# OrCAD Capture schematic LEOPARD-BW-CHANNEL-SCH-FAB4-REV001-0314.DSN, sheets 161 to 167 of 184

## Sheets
161 122_SMBUS (2/4): size A3; title: SMBUS (2/4)
162 124_SMBUS (4/4): size A3; title: SMBUS (4/4)
163 047_CPU2 - QPI (1/2): size A3; title: CPU2 - QPI (1/2)
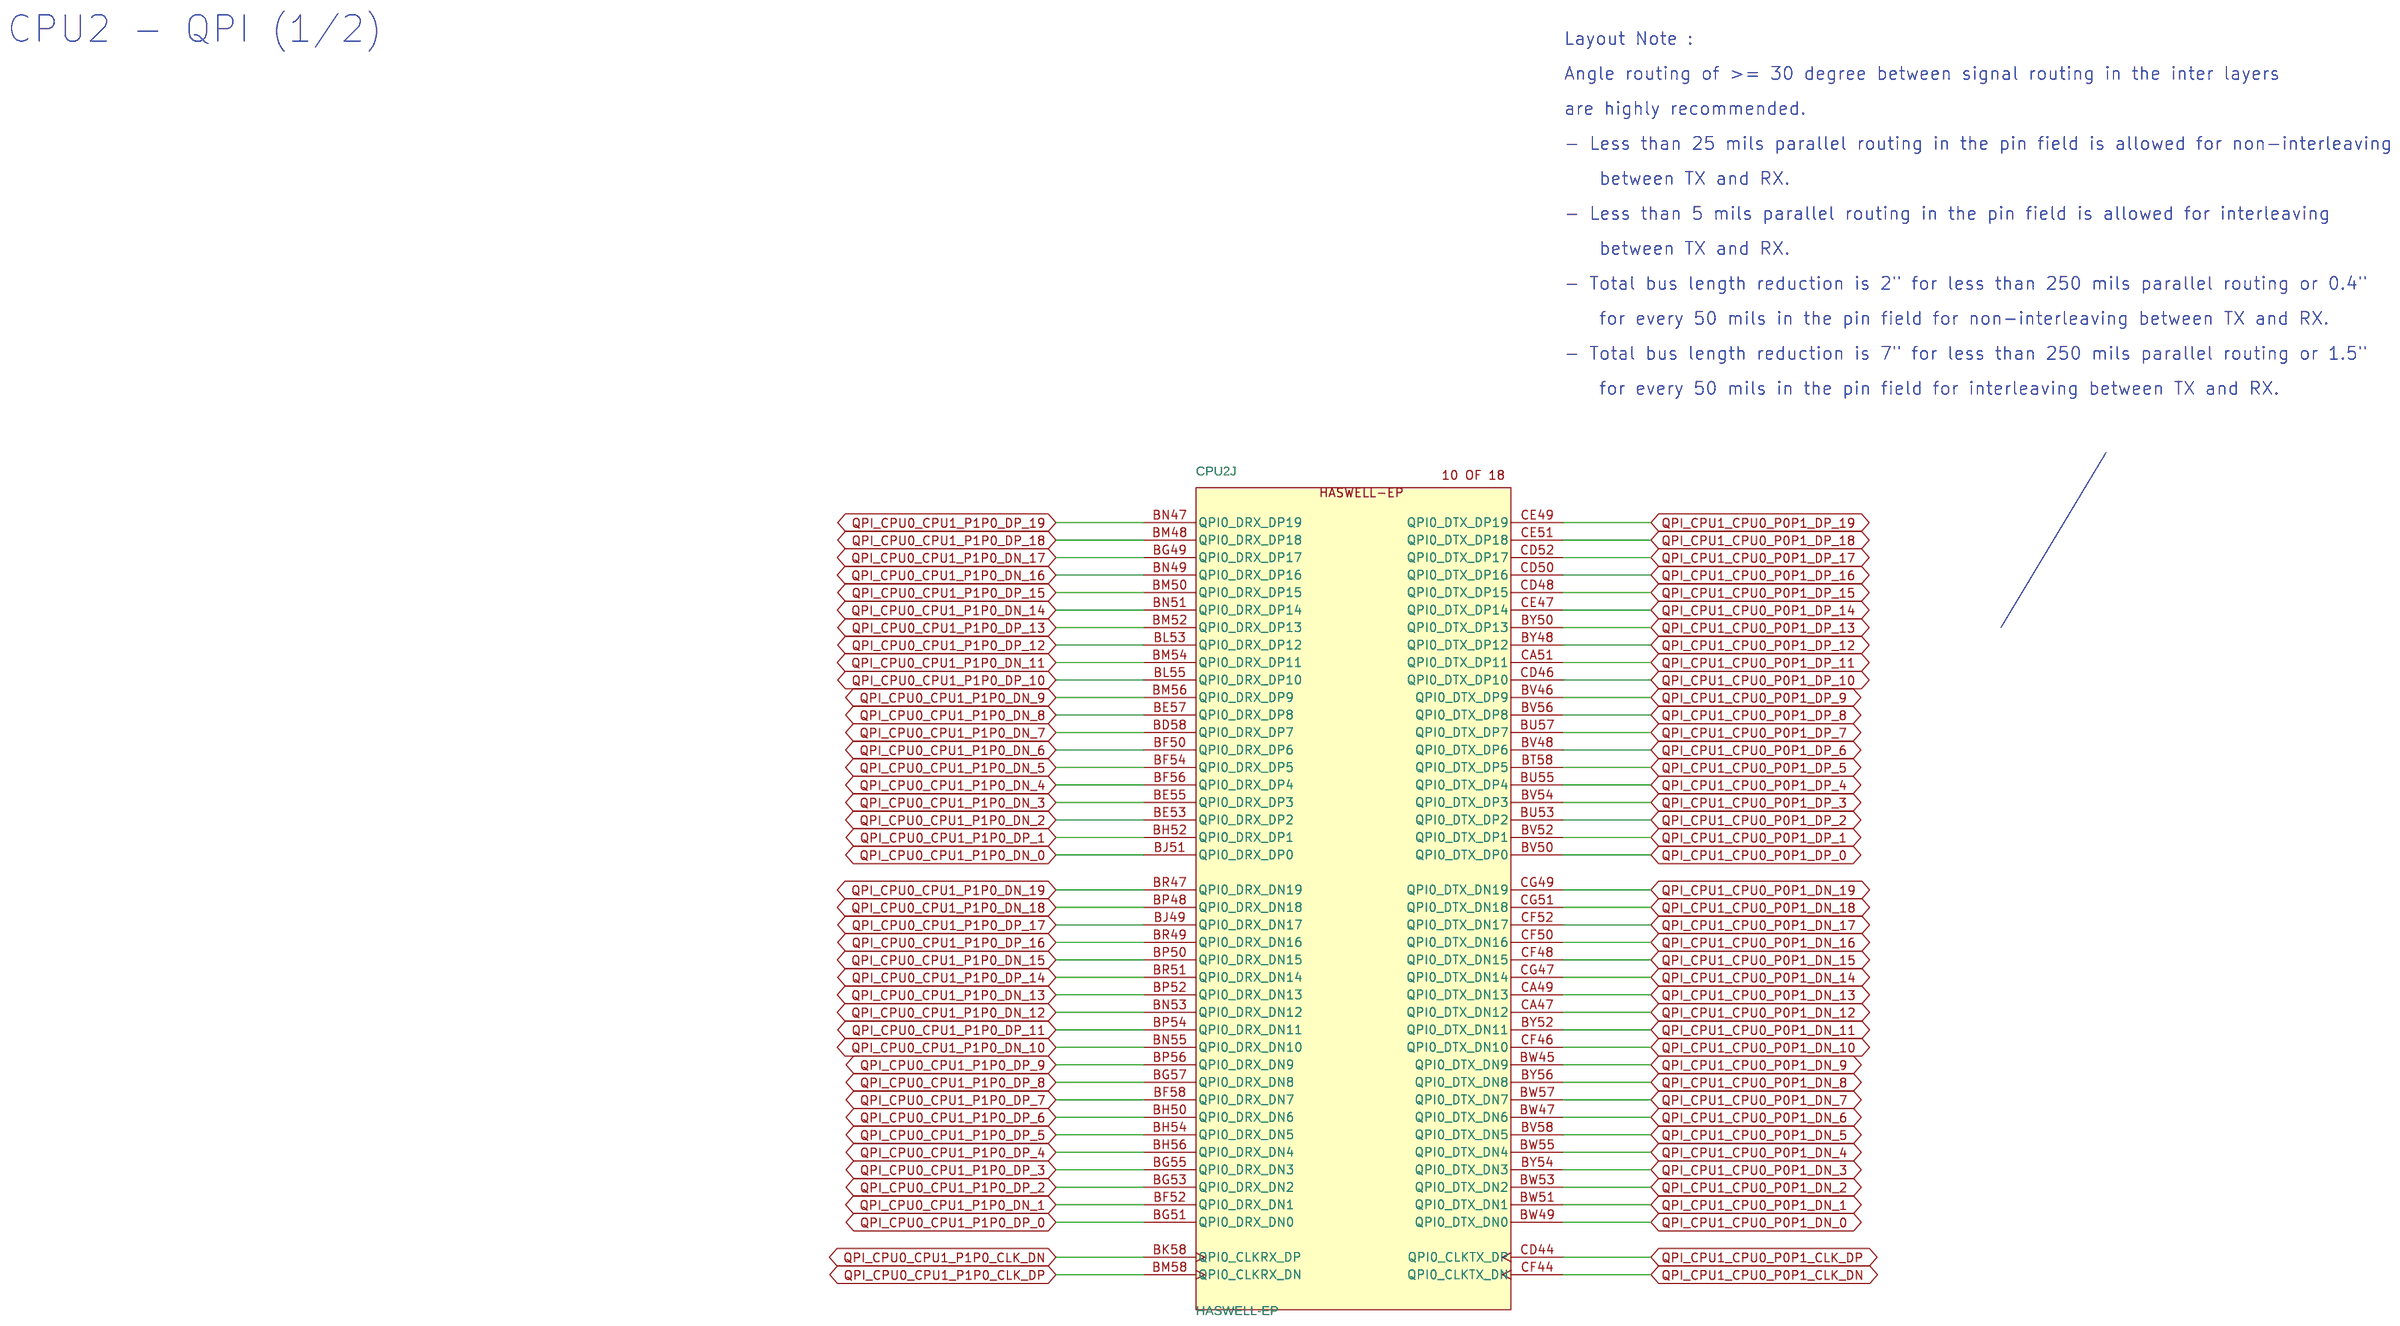
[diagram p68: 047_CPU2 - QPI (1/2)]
164 033_CPU1 - QPI (1/2): size A3; title: CPU1 - QPI (1/2)
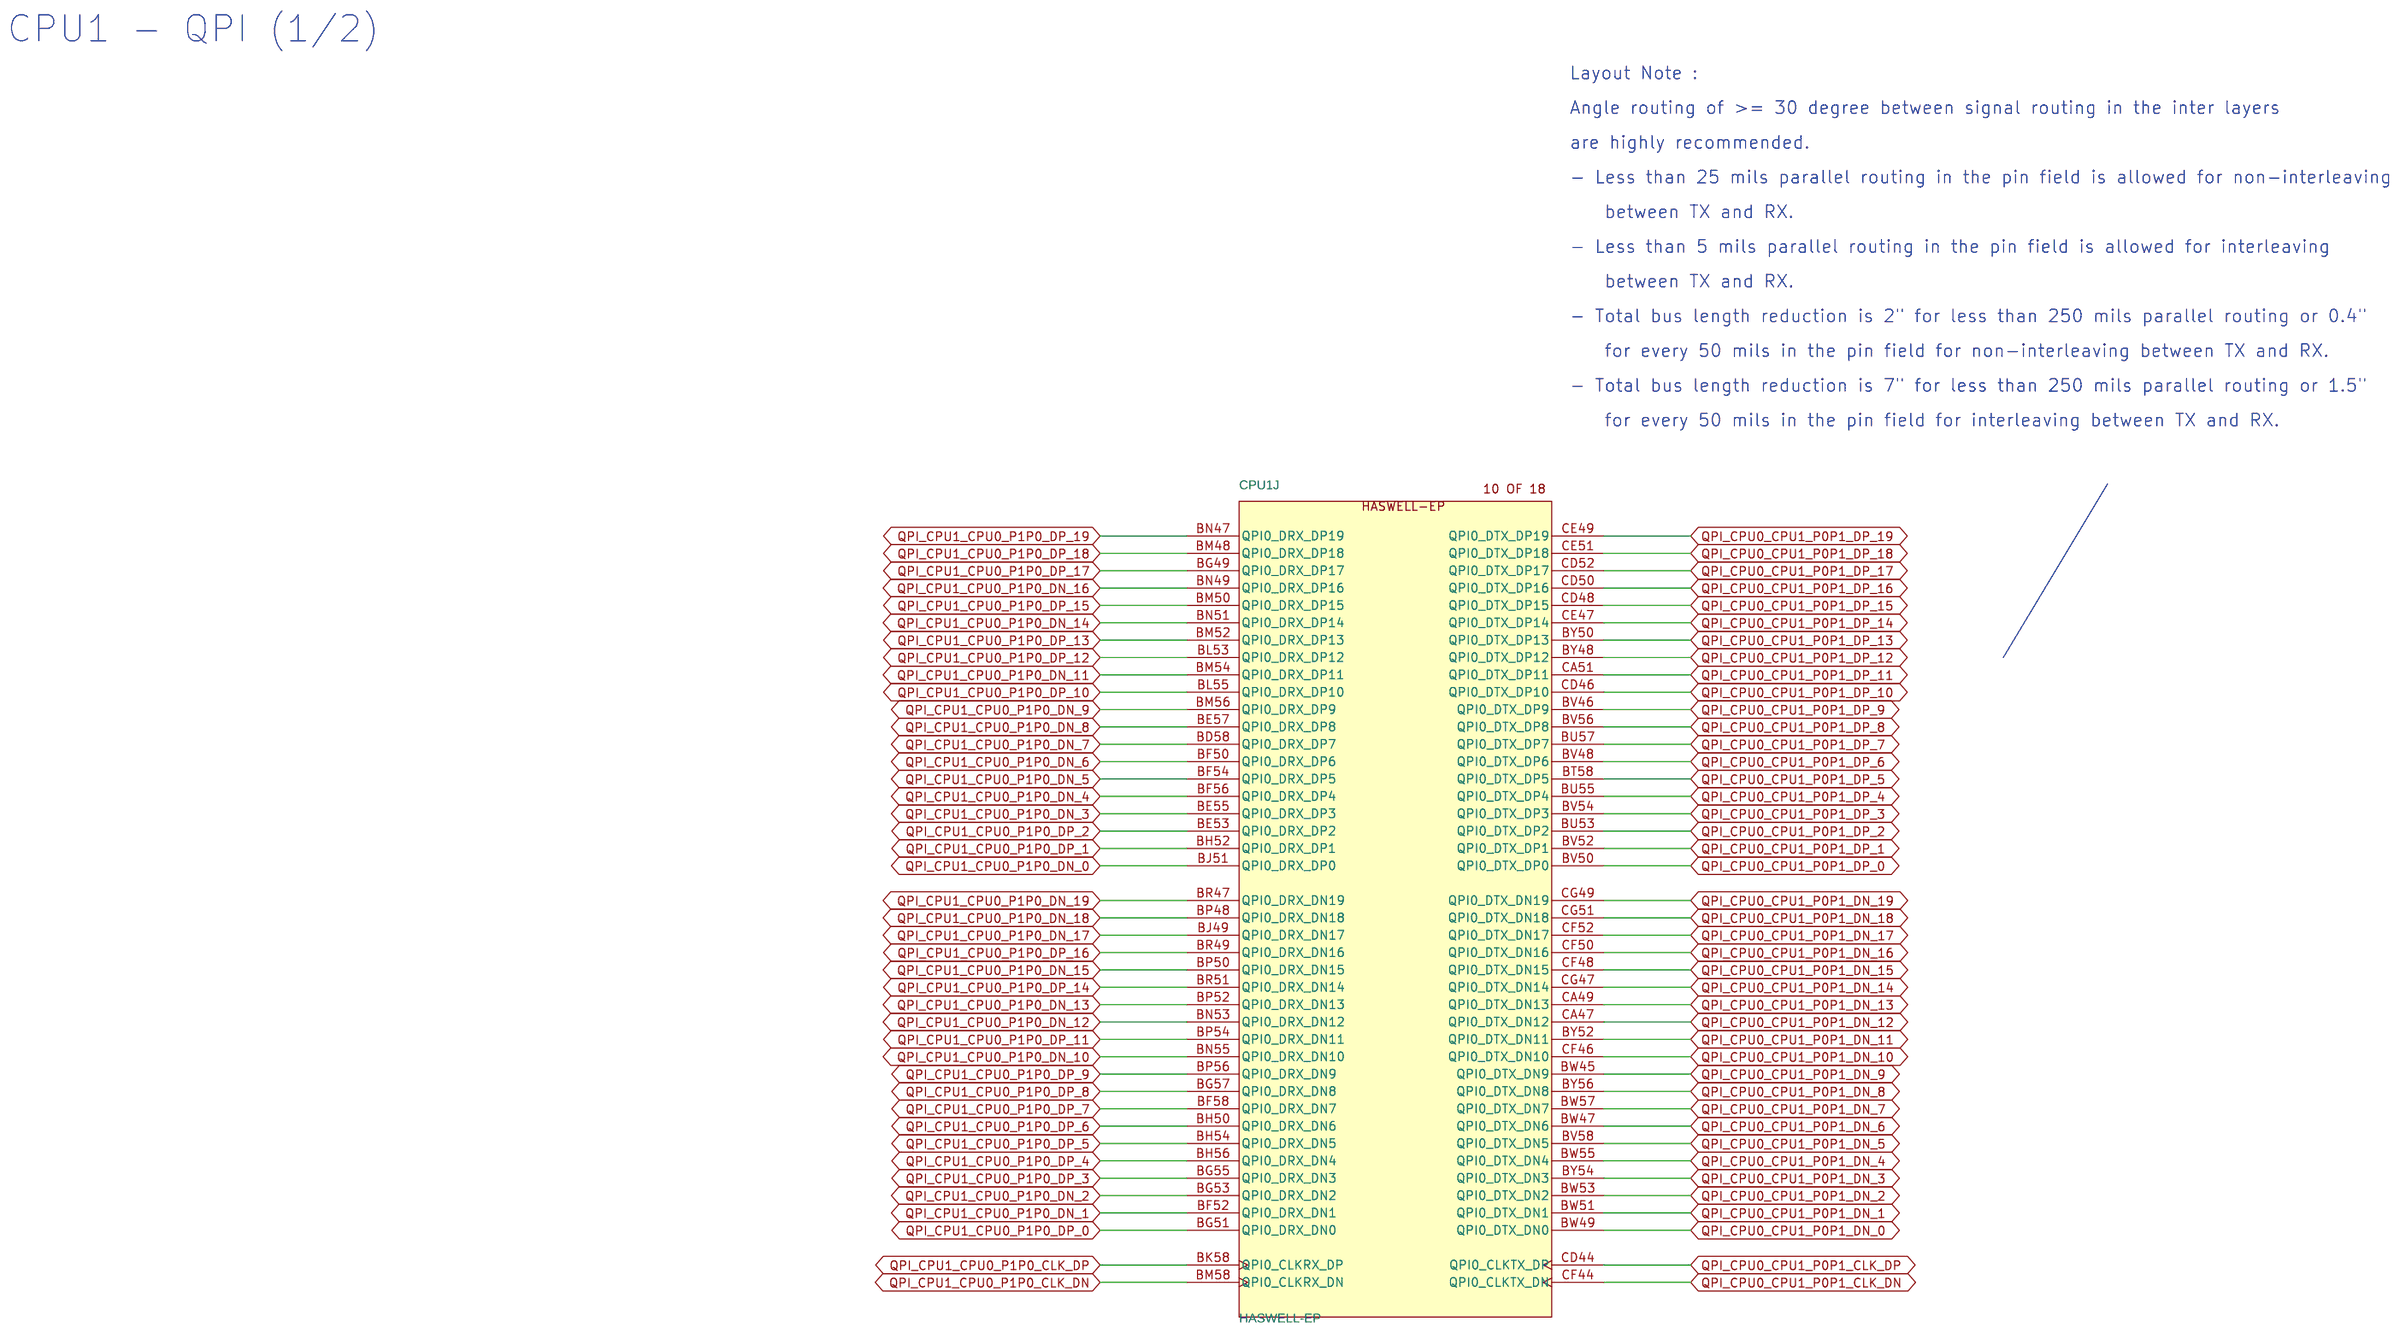
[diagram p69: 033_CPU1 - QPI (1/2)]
165 034_CPU1 - QPI (2/2): size A3; title: CPU1 - QPI (2/2)
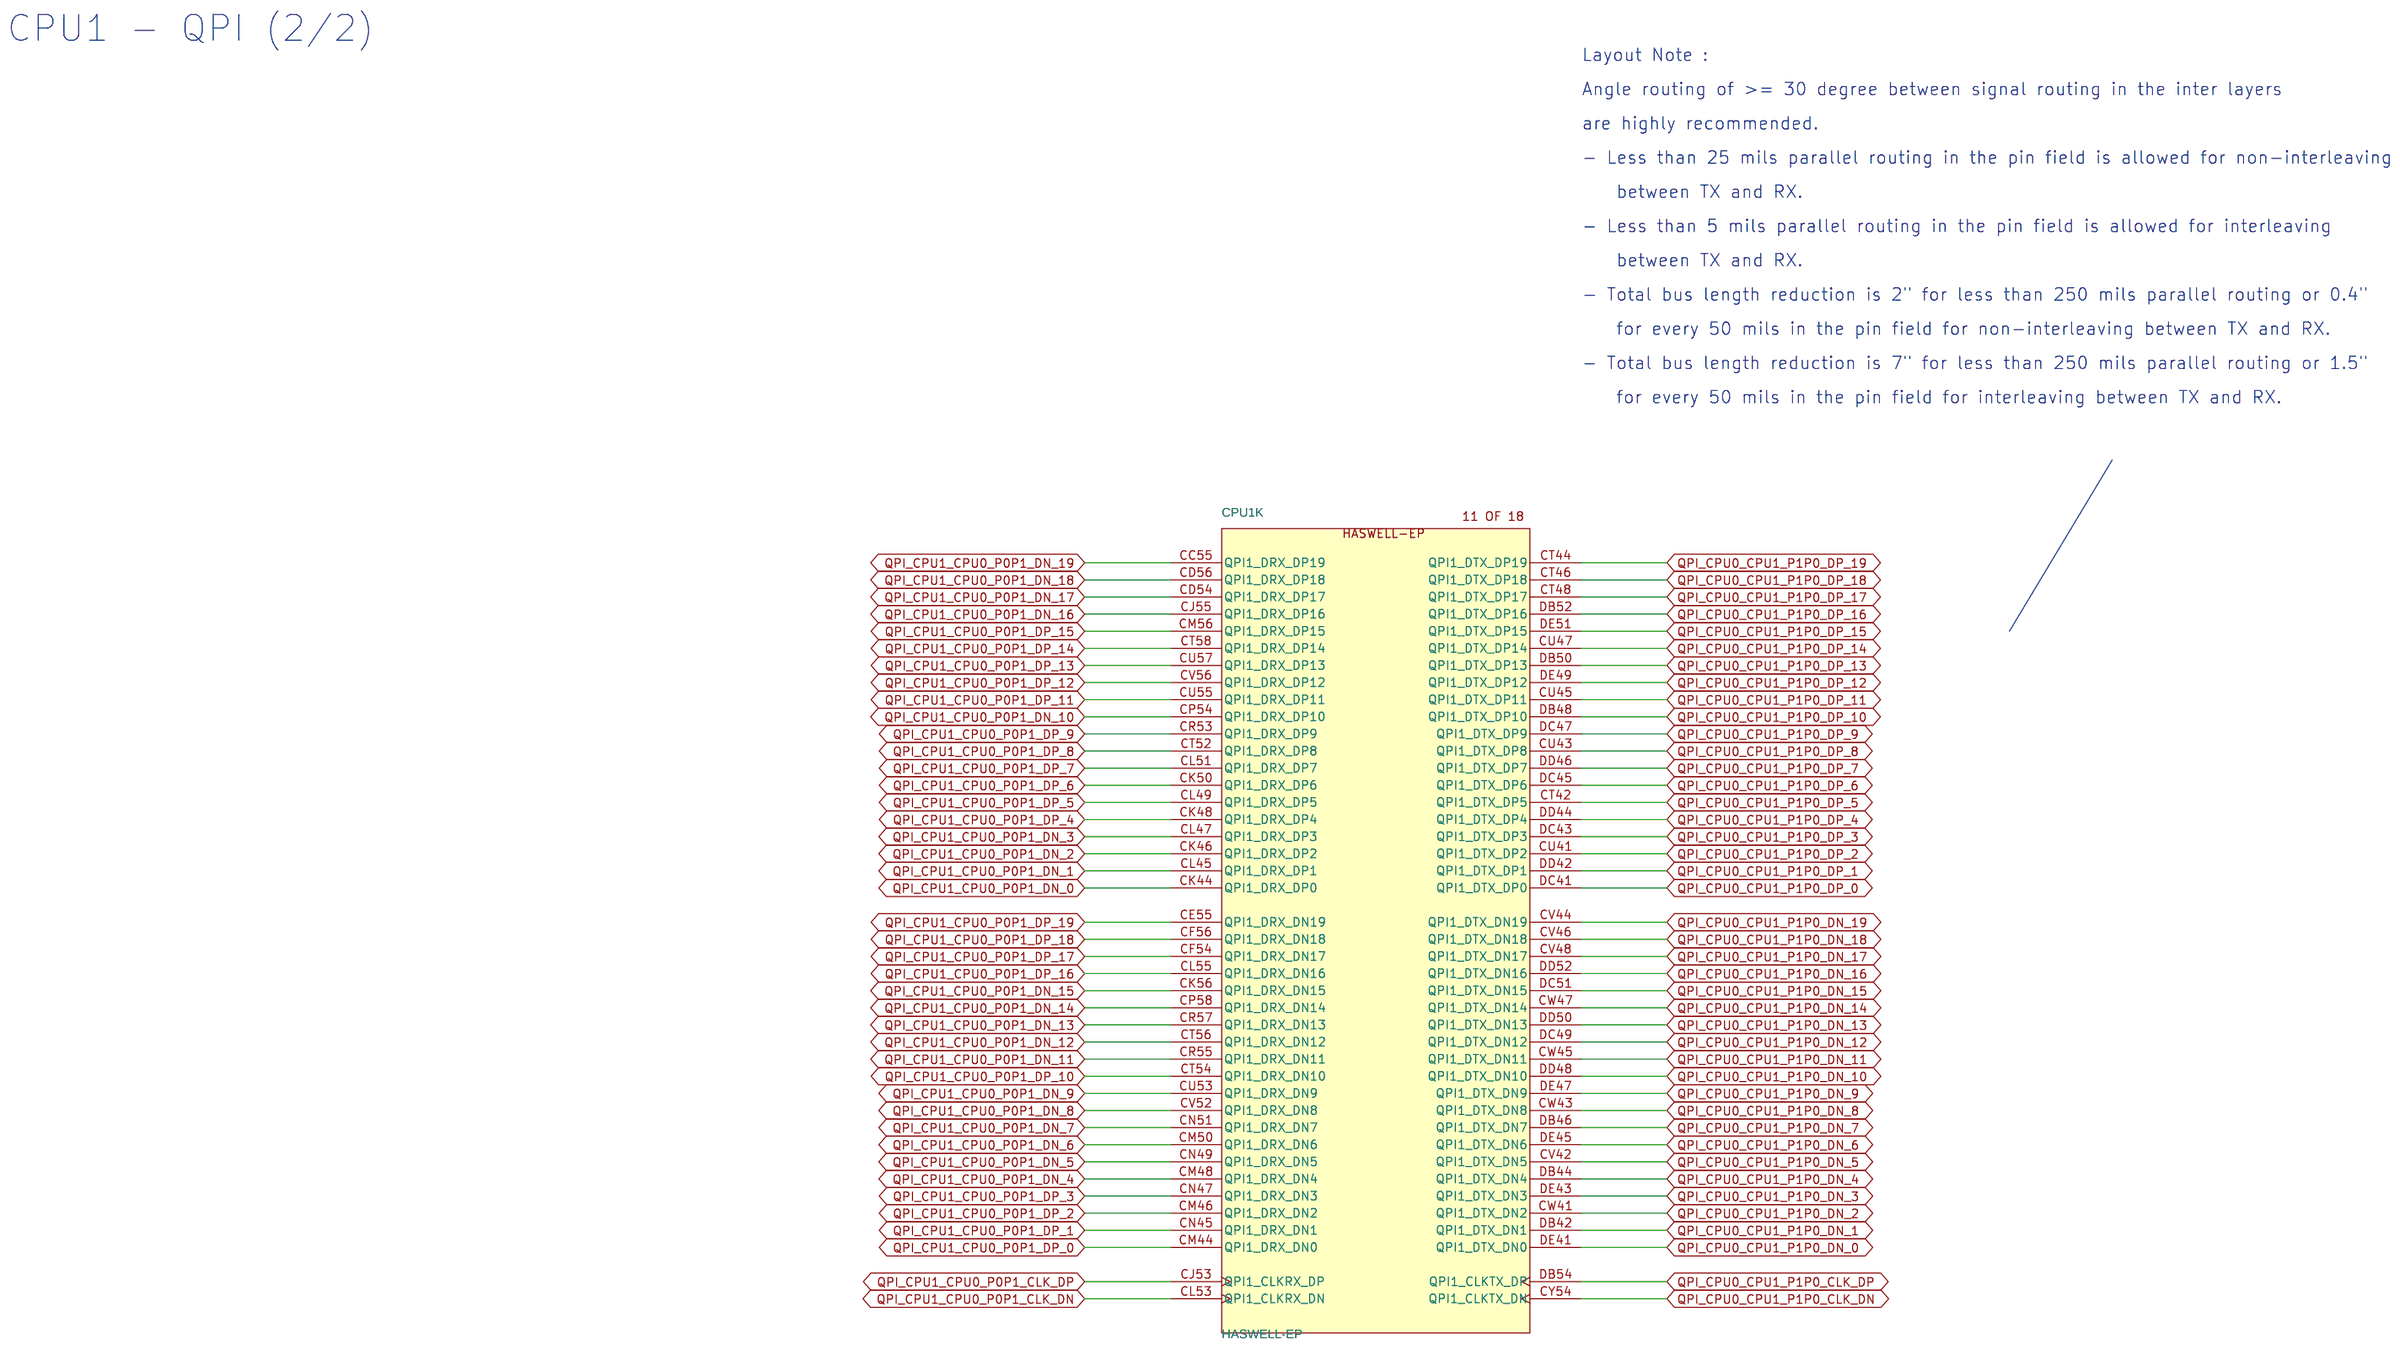
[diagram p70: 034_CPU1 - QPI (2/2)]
166 082_WBG - CLOCK/MICS: size A3; title: WBG - CLOCK/MICS
167 048_CPU2 - QPI (2/2): size A3; title: CPU2 - QPI (2/2)
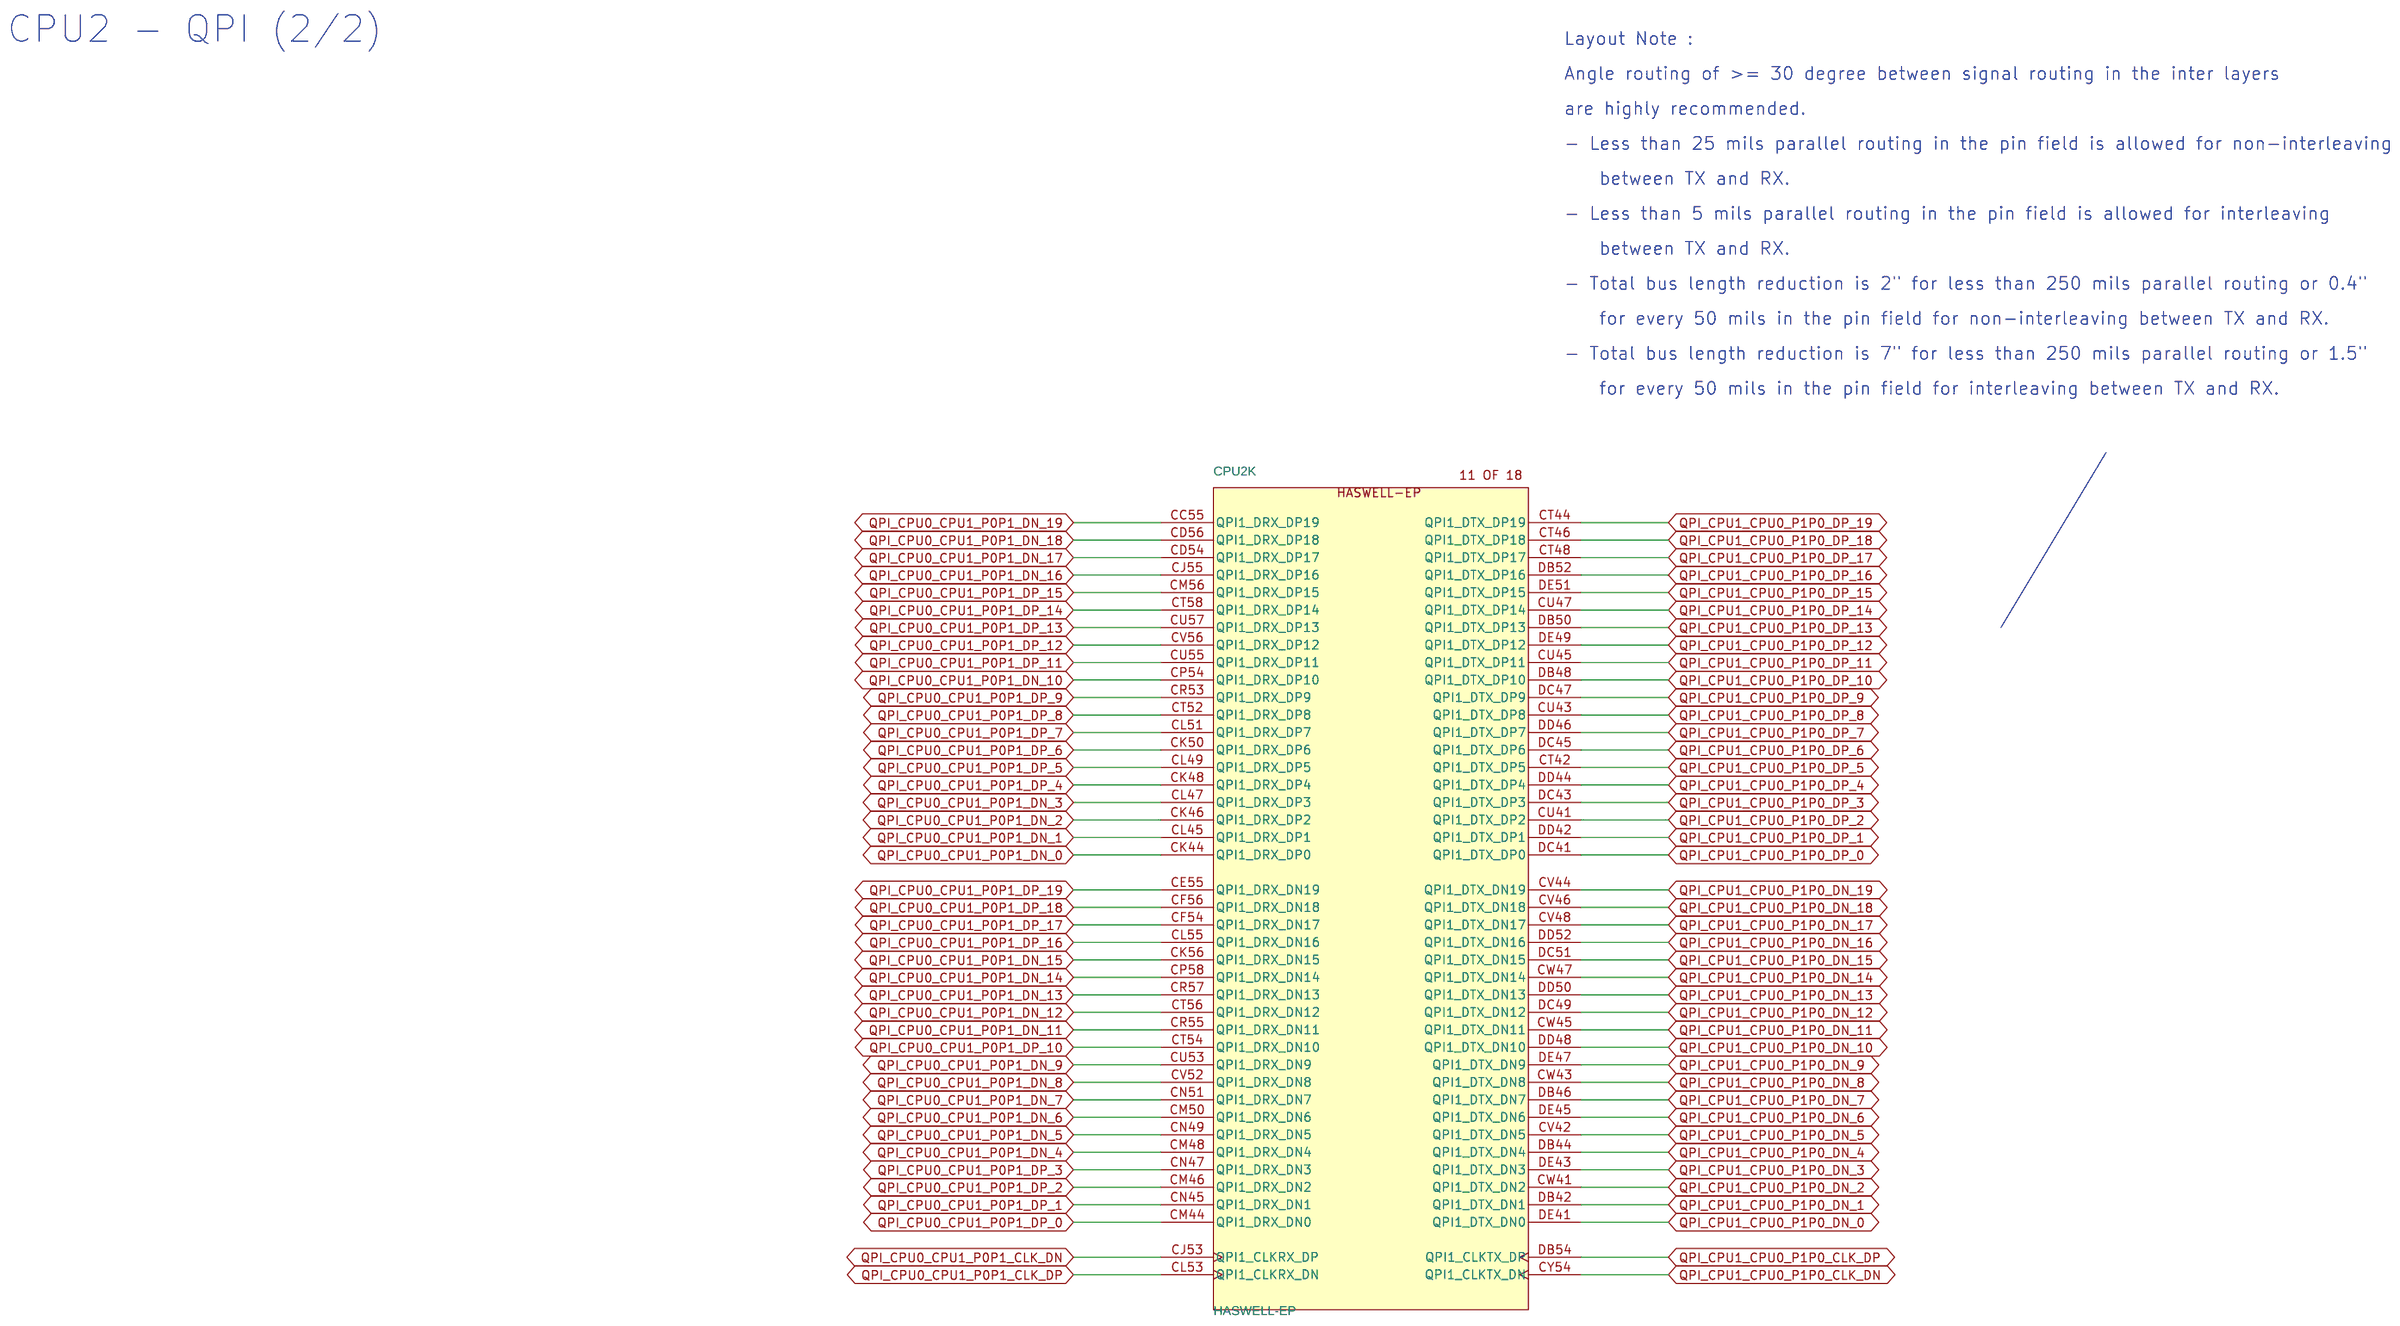
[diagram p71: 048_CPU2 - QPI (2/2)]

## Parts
sheet 035_CPU1 - VCCIN & VDDQ
CPU1  HASWELL-EP  [SKT-LGA2011M6151-1H298]  (sections A,B,C,D,E,F,G,H,I,J,K,L,M,N,O,P,Q,R)
sheet 041_CPU2 - DDR4 (CHANNEL F)
CPU2  HASWELL-EP  [SKT-LGA2011M6151-1H298]  (sections A,B,C,D,E,F,G,H,I,J,K,L,M,N,O,P,Q,R)
sheet 082_WBG - CLOCK/MICS
JP7  FCI-CON2-S-GP  [680001-202HLF]
R130  7K5R2F-1-GP  [R402H16]
R131  7K5R2F-1-GP  [R402H16]
R132  22D6R2F-L1-GP  [R402H16]
R133  7K5R2F-1-GP  [R402H16]
R134  10KR2F-2-GP  [R402H16]
R135  10KR2F-2-GP  [R402H16]
R136  7K5R2F-1-GP  [R402H16]
R137  10KR2F-2-GP  [R402H16]
R188  10KR2F-2-GP  [R402H16]
R193  10KR2F-2-GP  [R402H16]
R197  10KR2F-2-GP  [R402H16]
R251  2K2R2F-GP  [R402H16]
R256  1KR2F-3-GP  [R402H16]
R363  1KR2F-3-GP  [R402H16]
R365  10KR2F-2-GP  [R402H16]
R398  10KR2F-2-GP  [R402H16]
R499  0R2J-2-GP  [R402H16]
R706  10KR2F-2-GP  [R402H16]
R732  10KR2F-2-GP  [R402H16]
R843  10KR2F-2-GP  [R402H16]
R845  10KR2F-2-GP  [R402H16]
R847  10KR2F-2-GP  [R402H16]
R848  0R3J-0-U-GP  [R603H22]
R1206  10KR2F-2-GP  [R402H16]
TP184  TPAD24  [TPAD24]
sheet 083_WBG - DMI & USB
WBG1  WELLSBURG-1-GP-U  [BGA836M25H87]  (sections A,B,C,D,E,F,G,H,I,J,K)
sheet 122_SMBUS (2/4)
C505  SC1KP50V2KX-1GP  [C402H22]
C506  SC1KP50V2KX-1GP  [C402H22]
R616  1KR2F-3-GP  [R402H16]
R617  1KR2F-3-GP  [R402H16]
R618  4K7R2F-GP  [R402H16]
R619  4K7R2F-GP  [R402H16]
R622  4K7R2F-GP  [R402H16]
R623  4K7R2F-GP  [R402H16]
R874  1KR2F-3-GP  [R402H16]
R875  1KR2F-3-GP  [R402H16]
R876  4K7R2F-GP  [R402H16]
R877  4K7R2F-GP  [R402H16]
R878  4K7R2F-GP  [R402H16]
R879  4K7R2F-GP  [R402H16]
U41  NTJD4001NT1G-1-GP  [SOT-363H44]
sheet 124_SMBUS (4/4)
R717  0R2J-2-GP  [R402H16]
R721  0R2J-2-GP  [R402H16]

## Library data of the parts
CPU1 CPU2 = HASWELL-EP: SKT CPU LGA 2011P AZIF0001-P004C SMD; GREENDFACTOR: R2_C;; POP?: 62.10079.311; Package Type: SOCKET-G2; Part Number: 62.10079.261; SPEC: http://wpqssvr.wistron.com.tw:7001/wpqs/servlet/COM.qpart.Attachment?PartNumber=62.10079.261
JP7 = FCI-CON2-S-GP: HEAD ML 1R2P 68001-202HLF; GREENDFACTOR: R2_SA;; Part Number: 21.65007.102; Part Type: CONN-G4; SPEC: http://wpqssvr.wistron.com.tw:7001/wpqs/servlet/COM.qpart.Attachment?PartNumber=21.65007.102
R130 R131 R133 R136 = 7K5R2F-1-GP: CHIP RES 7.5K F 1/16W 0402; Category: PCH; Part Number: 64.75015.6DL; Part Type: SMD-RG
R132 = 22D6R2F-L1-GP: CHIP RES 22.6 F 1/16W 0402; Category: PCH; GREENDFACTOR: R2_SA;HF_SA;G_SA;; Package Type: SMD-RG; Part Number: 64.22R65.6DL; Quotation: 2_3; Type: SMD
R134 R135 R137 R188 R193 R197 R398 R1206 = 10KR2F-2-GP: CHIP RES 10K F 1/16W 0402; Category: PCH; DESCRIPTIO: CHIP RES 10K F 1/16W 0402; GREENDFACTOR: R2_SA;HF_SA;G_SA;; Package Type: SMD-RG; Part Number: 64.10025.6DL; Part Type: SMD-RG; SPEC: http://wpqssvr.wistron.com.tw:7001/wpqs/servlet/COM.qpart.Attachment?PartNumber=64.10025.6DL; VENDORPARTNUMBER: RM04FTN1002 / RTT021002FTH / RR0510S-103-FN / RC0402FR-0710KL/WR04X1002FTL
R251 = 2K2R2J-2-GP: CHIP RES 2.2K F 1/16W 0402; Category: BMC; DESCRIPTIO: CHIP RES 2.2K J 1/16W 0402; GREENDFACTOR: R2_SA;HF_SA;G_SA;; Package Type: RCL_GP; Part Number: 64.22015.6DL; Part Type: RCL_GP; SPEC: http://wpqssvr.wistron.com.tw:7001/wpqs/servlet/COM.qpart.Attachment?PartNumber=64.22015.6DL; VENDORPARTNUMBER: RM04FTN2201/RTT022201FTH/RR0510S-222-FN/RC0402FR-072K2L
R256 = 1KR2F-3-GP: CHIP RES 1K F 1/16W 0402; Category: PCH; GREENDFACTOR: R2_SA;HF_SA;G_SA;; Package Type: SMD-RG; Part Number: 64.10015.6DL; Part Type: SMD-RG; SPEC: http://wpqssvr.wistron.com.tw:7001/wpqs/servlet/COM.qpart.Attachment?PartNumber=64.10015.6DL; VENDORPARTNUMBER: RM04FTN1001 / RTT021001FTH / RR0510S-1001-FN / RC0402FR-071KL/WR04X1001FTL
R363 = 1KR2F-3-GP: CHIP RES 1K F 1/16W 0402; GREENDFACTOR: R2_SA;HF_SA;G_SA;; Package Type: SMD-RG; Part Number: 64.10015.6DL; SPEC: http://wpqssvr.wistron.com.tw:7001/wpqs/servlet/COM.qpart.Attachment?PartNumber=64.10015.6DL
R365 R706 = 10KR2F-2-GP: CHIP RES 10K F 1/16W 0402; Category: PCH; DESCRIPTIO: CHIP RES 10K F 1/16W 0402; GREENDFACTOR: R2_SA;HF_SA;G_SA;; POP?: NOPOP; Package Type: SMD-RG; Part Number: 64.10025.6DL; Part Type: SMD-RG; SPEC: http://wpqssvr.wistron.com.tw:7001/wpqs/servlet/COM.qpart.Attachment?PartNumber=64.10025.6DL; VENDORPARTNUMBER: RM04FTN1002 / RTT021002FTH / RR0510S-103-FN / RC0402FR-0710KL/WR04X1002FTL
R499 = 0R2J-2-GP: CHIP RES 0 J 1/16W 0402; GREENDFACTOR: R2_SA;HF_SA;G_SA;; Package Type: SMD-RG; Part Number: 63.R0034.1DL; SPEC: http://wpqssvr.wistron.com.tw:7001/wpqs/servlet/COM.qpart.Attachment?PartNumber=63.R0034.1DL
R732 R843 R845 R847 = 10KR2F-2-GP: CHIP RES 10K F 1/16W 0402; GREENDFACTOR: R2_SA;HF_SA;G_SA;; Package Type: SMD-RG; Part Number: 64.10025.6DL; SPEC: http://wpqssvr.wistron.com.tw:7001/wpqs/servlet/COM.qpart.Attachment?PartNumber=64.10025.6DL
R848 = 0R3J-0-U-GP: CHIP RES 0 J 1/10W 0603; Category: USB; DESCRIPTIO: CHIP RES 0 J 1/10W 0603; GREENDFACTOR: R2_SA;HF_SA;G_SA;; Package Type: RCL_GP; Part Number: 63.00000.00L; Part Type: RCL_GP; SPEC: http://wpqssvr.wistron.com.tw:7001/wpqs/servlet/COM.qpart.Attachment?PartNumber=63.00000.00L; VENDORPARTNUMBER: RM06JTN0 / RTT03000JTP / RC0603JR-070RL / WR06X000 PTL
TP184 = TPAD24: 24 MILS TEST PAD; Category: PCH; Part Number: ZZ.PAD24.001; Part Type: DISCRET2
WBG1 = WELLSBURG-1-GP-U: IC PCH WELLSBURG FCBGA 836P(SERVER); GREENDFACTOR: R2_C;; POP?: 071.82029.0B0U; Package Type: ASIC2-G4; Part Number: 71.WSBUG.00U; SPEC: http://wpqssvr.wistron.com.tw:7001/wpqs/servlet/COM.qpart.Attachment?PartNumber=71.WSBUG.00U
C505 C506 = SC1KP50V2KX-1GP: CHIP CAP 1000P50V K0402 X7R(RO; CATEGORIES: CAP_Small; Category: MSIC; DESCRIPTIO: CHIP CAP 1000P50V K0402 X7R(RO; GREENDFACTOR: R2_SA;HF_SA;G_SA;; MAIN_SOURCE: M; Package Type: SMD-BCG; Part Number: 78.10224.2FL; Part Type: SMD-BCG; SPEC: http://wpqssvr.wistron.com.tw:7001/wpqs/servlet/COM.qpart.Attachment?PartNumber=78.10224.2FL; VENDORPARTNUMBER: CM05X7R102K50AH/C1005X7R102KGT/GRM155R71H102KA01D/223858715623/CL05B102KB5NNNC/UMK105BJ102KV-F/C1005X7R1H102KT000F
R616 R617 R874 R875 = 1KR2F-3-GP: CHIP RES 1K F 1/16W 0402; Category: PCH; DESCRIPTIO: CHIP RES 1K F 1/16W 0402; GREENDFACTOR: R2_SA;HF_SA;G_SA;; Package Type: SMD-RG; Part Number: 64.10015.6DL; Part Type: SMD-RG; SPEC: http://wpqssvr.wistron.com.tw:7001/wpqs/servlet/COM.qpart.Attachment?PartNumber=64.10015.6DL; VENDORPARTNUMBER: RM04FTN1001 / RTT021001FTH / RR0510S-1001-FN / RC0402FR-071KL/WR04X1001FTL
R618 R619 R622 R623 R876-R879 = 4K7R2F-GP: CHIP RES 4.7K F 1/16W 0402; Category: LOM - i350; DESCRIPTIO: CHIP RES 4.7K F 1/16W 0402; GREENDFACTOR: R2_SA;HF_SA;G_SA;; Package Type: RCL_GP; Part Number: 64.47015.6DL; Part Type: RCL_GP; SPEC: http://wpqssvr.wistron.com.tw:7001/wpqs/servlet/COM.qpart.Attachment?PartNumber=64.47015.6DL; VENDORPARTNUMBER: RM04FTN4701/RTT024701FTH/RR0510S-472-FN/RC0402FR-074K7L/WR04X4701FTL
U41 = NTJD4001NT1G-1-GP: IC MOSFET NTJD4001NT1G NC SOT-363 6P; GREENDFACTOR: R2_SA;; Part Number: 75.04001.07C; Part Type: DISCRET-G5; SPEC: http://wpqssvr.wistron.com.tw:7001/wpqs/servlet/COM.qpart.Attachment?PartNumber=75.04001.07C
R717 R721 = 0R2J-2-GP: CHIP RES 0 J 1/16W 0402; Category: LOM - i350; DESCRIPTIO: CHIP RES 0 J 1/16W 0402; GREENDFACTOR: R2_SA;HF_SA;G_SA;; Package Type: SMD-RG; Part Number: 63.R0034.1DL; Part Type: SMD-RG; SPEC: http://wpqssvr.wistron.com.tw:7001/wpqs/servlet/COM.qpart.Attachment?PartNumber=63.R0034.1DL; VENDORPARTNUMBER: RM04JTN0/RTT02000JTH/RR0510X-000-XN/RC0402JR-070RL/WR04X000 PTL

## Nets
GND: C505.2 C506.2 R132.2 R256.2 R363.2 R732.1 R843.1 R845.1 R847.1 ; also on sheet 1 2 3 4 5 6 7 8 9 10 11 12 13 14 15 16 17 18 19 20 21 22 23 24 25 26 27 28 29 30 31 32 33 34 35 36 37 38 39 44 46 47 49 50 51 52 53 54 55 56 57 58 59 60 61 62 63 64 65 66 69 70 71 73 74 75 76 78 79 80 81 82 83 84 86 87 88 89 90 91 92 93 94 95 96 97 98 99 100 101 102 103 104 105 106 107 108 109 110 111 112 113 114 115 116 117 118 119 128 129 138 139 159 160 168 169 170 171 172 173 174 175 176 177 180 181 182 183 184
P1V5_PCH: R130.2 R131.2 R133.1 R136.1 WBG1.AC1(PCIE_IREF) WBG1.BD32(SSATA_IREF) WBG1.L12(SATA_IREF) WBG1.V15(DMI_IREF) ; also on sheet 8 45 87 91 173
P1V05_VCCRTCEXT: WBG1.N35(DCPRTC) ; also on sheet 173
P3V3: R134.2 R135.2 R137.2 R188.1 R193.1 R197.1 R251.2 R365.2 R398.2 R616.1 R617.1 R618.1 R619.1 R622.1 R623.1 R706.2 R876.1 R877.1 R878.1 R879.1 ; also on sheet 1 3 8 45 46 48 49 52 54 58 65 74 76 78 83 84 87 90 91 94 95 96 100 101 102 168 173 174 177 180 181 182 183
P3V3_STBY: R874.1 R875.1 R1206.2 ; also on sheet 2 3 5 6 8 9 10 11 12 15 16 17 20 21 22 25 26 27 30 31 33 34 35 37 38 39 45 47 49 50 51 52 54 55 59 60 61 62 63 64 65 66 69 70 71 72 73 74 76 79 83 84 87 88 89 90 91 92 93 94 95 96 97 98 99 159 168 173 174 176 177 179 180 182 183 184
BIOS_ERR_TRIGGER_N: R251.1 WBG1.AB48(PIRQG#/GPIO4) ; also on sheet 65 177
BMC_READY_C: R499.1 WBG1.F27(GPIO47)
CLK_33M_PCH: WBG1.AE47(CLKIN_PCILOOPBACK) ; also on sheet 88
CLK_100M_PCH_SATA_DN: R843.2 WBG1.D20(CLKIN_SATA_N)
CLK_100M_PCH_SATA_DP: R732.2 WBG1.B20(CLKIN_SATA_P)
CLK_100M_PCH_SATAX_DN: R847.2 WBG1.BC38(CLKIN_SSATA_N)
CLK_100M_PCH_SATAX_DP: R845.2 WBG1.BD38(CLKIN_SSATA_P)
DMI_PCH_DMI_RCOMP: R133.2 WBG1.T15(DMI_RCOMP)
FET_SMB_HOST_CLK: C505.1 R616.2 U41.5(G2)
FET_SMB_HOST_DATA: C506.1 R617.2 U41.2(G1)
FM_ADR_COMPLETE: R848.2 ; also on sheet 51 177
FM_ADR_COMPLETE_R: R848.1 WBG1.D46(RESERVED#D46)
FM_BMC_READY_N: R499.2 R1206.1 ; also on sheet 51 52 74
FM_CPU_ERR0_CO_N: R197.2 WBG1.Y48(PIRQE#/GPIO2) ; also on sheet 102 177
FM_ERR1_DLY_N: R188.2 WBG1.AD48(PIRQF#/GPIO3) ; also on sheet 51
FM_MGPIO14: WBG1.BF28(MGPIO14) ; also on sheet 84
FM_MGPIO15: WBG1.BH28(MGPIO15) ; also on sheet 84
FM_MGPIO16: WBG1.BF26(MGPIO16) ; also on sheet 84
FM_MGPIO17: WBG1.BJ29(MGPIO17) ; also on sheet 84
FM_PCIE_SLOT_CPRSNT1_N: WBG1.U49(GPIO54/GSXSRESET#) ; also on sheet 94
FM_PMBUS_ALERT_BUF_EN: R706.1 WBG1.BH26(MGPIO13) ; also on sheet 52 84
IRQ_CPU_CATERR_DLY: WBG1.Y46(PIRQH#/GPIO5) ; also on sheet 100
PCH_GP56_PLD_TCK: WBG1.M29(GPIO56) ; also on sheet 51
PCIE_PCH_PCIE_RCOMP: R136.2 WBG1.AG12(PCIE_RCOMP)
PCIE_SLOT0_CONFIG: WBG1.L34(GPIO52/GSXSLOAD) ; also on sheet 94
PCIE_SLOT1_CONFIG: WBG1.J34(GPIO50/GSXCLK) ; also on sheet 94
PD_GSXDIN: R363.1 WBG1.V48(GPIO53/GSXDIN)
PD_PCH_GP51_GSXDOUT: WBG1.L32(GPIO51/GSXDOUT) ; also on sheet 174
PD_PCH_USBCOMP: R132.1 WBG1.AP40(USBRBIAS#) WBG1.AP41(USBRBIAS)
PD_TOP_SWAP: JP7.2 R256.1
PU_PCH_GPIO55: JP7.1 R398.1 WBG1.J23(GPIO55)
PU_PCI_PIRQA_N: R134.1 WBG1.AA47(PIRQA#)
PU_PCI_PIRQB_N: R135.1 WBG1.AA49(PIRQB#)
PU_PCI_PIRQC_N: R137.1 WBG1.AE49(PIRQC#)
PU_PCI_PIRQD_N: R193.2 WBG1.AF48(PIRQD#)
PU_SATA_PCH_SATA_RCOMP: R130.1 WBG1.N10(SATA_RCOMP)
PU_SATA_PCH_SATAX_RCOMP: R131.1 WBG1.BC32(SSATA_RCOMP)
QPI_CPU0_CPU1_P0P1_CLK_DN: CPU1.CF44(QPI0_CLKTX_DN) CPU2.CJ53(QPI1_CLKRX_DP)
QPI_CPU0_CPU1_P0P1_CLK_DP: CPU1.CD44(QPI0_CLKTX_DP) CPU2.CL53(QPI1_CLKRX_DN)
QPI_CPU0_CPU1_P0P1_DN_0: CPU1.BW49(QPI0_DTX_DN0) CPU2.CK44(QPI1_DRX_DP0)
QPI_CPU0_CPU1_P0P1_DN_1: CPU1.BW51(QPI0_DTX_DN1) CPU2.CL45(QPI1_DRX_DP1)
QPI_CPU0_CPU1_P0P1_DN_2: CPU1.BW53(QPI0_DTX_DN2) CPU2.CK46(QPI1_DRX_DP2)
QPI_CPU0_CPU1_P0P1_DN_3: CPU1.BY54(QPI0_DTX_DN3) CPU2.CL47(QPI1_DRX_DP3)
QPI_CPU0_CPU1_P0P1_DN_4: CPU1.BW55(QPI0_DTX_DN4) CPU2.CM48(QPI1_DRX_DN4)
QPI_CPU0_CPU1_P0P1_DN_5: CPU1.BV58(QPI0_DTX_DN5) CPU2.CN49(QPI1_DRX_DN5)
QPI_CPU0_CPU1_P0P1_DN_6: CPU1.BW47(QPI0_DTX_DN6) CPU2.CM50(QPI1_DRX_DN6)
QPI_CPU0_CPU1_P0P1_DN_7: CPU1.BW57(QPI0_DTX_DN7) CPU2.CN51(QPI1_DRX_DN7)
QPI_CPU0_CPU1_P0P1_DN_8: CPU1.BY56(QPI0_DTX_DN8) CPU2.CV52(QPI1_DRX_DN8)
QPI_CPU0_CPU1_P0P1_DN_9: CPU1.BW45(QPI0_DTX_DN9) CPU2.CU53(QPI1_DRX_DN9)
QPI_CPU0_CPU1_P0P1_DN_10: CPU1.CF46(QPI0_DTX_DN10) CPU2.CP54(QPI1_DRX_DP10)
QPI_CPU0_CPU1_P0P1_DN_11: CPU1.BY52(QPI0_DTX_DN11) CPU2.CR55(QPI1_DRX_DN11)
QPI_CPU0_CPU1_P0P1_DN_12: CPU1.CA47(QPI0_DTX_DN12) CPU2.CT56(QPI1_DRX_DN12)
QPI_CPU0_CPU1_P0P1_DN_13: CPU1.CA49(QPI0_DTX_DN13) CPU2.CR57(QPI1_DRX_DN13)
QPI_CPU0_CPU1_P0P1_DN_14: CPU1.CG47(QPI0_DTX_DN14) CPU2.CP58(QPI1_DRX_DN14)
QPI_CPU0_CPU1_P0P1_DN_15: CPU1.CF48(QPI0_DTX_DN15) CPU2.CK56(QPI1_DRX_DN15)
QPI_CPU0_CPU1_P0P1_DN_16: CPU1.CF50(QPI0_DTX_DN16) CPU2.CJ55(QPI1_DRX_DP16)
QPI_CPU0_CPU1_P0P1_DN_17: CPU1.CF52(QPI0_DTX_DN17) CPU2.CD54(QPI1_DRX_DP17)
QPI_CPU0_CPU1_P0P1_DN_18: CPU1.CG51(QPI0_DTX_DN18) CPU2.CD56(QPI1_DRX_DP18)
QPI_CPU0_CPU1_P0P1_DN_19: CPU1.CG49(QPI0_DTX_DN19) CPU2.CC55(QPI1_DRX_DP19)
QPI_CPU0_CPU1_P0P1_DP_0: CPU1.BV50(QPI0_DTX_DP0) CPU2.CM44(QPI1_DRX_DN0)
QPI_CPU0_CPU1_P0P1_DP_1: CPU1.BV52(QPI0_DTX_DP1) CPU2.CN45(QPI1_DRX_DN1)
QPI_CPU0_CPU1_P0P1_DP_2: CPU1.BU53(QPI0_DTX_DP2) CPU2.CM46(QPI1_DRX_DN2)
QPI_CPU0_CPU1_P0P1_DP_3: CPU1.BV54(QPI0_DTX_DP3) CPU2.CN47(QPI1_DRX_DN3)
QPI_CPU0_CPU1_P0P1_DP_4: CPU1.BU55(QPI0_DTX_DP4) CPU2.CK48(QPI1_DRX_DP4)
QPI_CPU0_CPU1_P0P1_DP_5: CPU1.BT58(QPI0_DTX_DP5) CPU2.CL49(QPI1_DRX_DP5)
QPI_CPU0_CPU1_P0P1_DP_6: CPU1.BV48(QPI0_DTX_DP6) CPU2.CK50(QPI1_DRX_DP6)
QPI_CPU0_CPU1_P0P1_DP_7: CPU1.BU57(QPI0_DTX_DP7) CPU2.CL51(QPI1_DRX_DP7)
QPI_CPU0_CPU1_P0P1_DP_8: CPU1.BV56(QPI0_DTX_DP8) CPU2.CT52(QPI1_DRX_DP8)
QPI_CPU0_CPU1_P0P1_DP_9: CPU1.BV46(QPI0_DTX_DP9) CPU2.CR53(QPI1_DRX_DP9)
QPI_CPU0_CPU1_P0P1_DP_10: CPU1.CD46(QPI0_DTX_DP10) CPU2.CT54(QPI1_DRX_DN10)
QPI_CPU0_CPU1_P0P1_DP_11: CPU1.CA51(QPI0_DTX_DP11) CPU2.CU55(QPI1_DRX_DP11)
QPI_CPU0_CPU1_P0P1_DP_12: CPU1.BY48(QPI0_DTX_DP12) CPU2.CV56(QPI1_DRX_DP12)
QPI_CPU0_CPU1_P0P1_DP_13: CPU1.BY50(QPI0_DTX_DP13) CPU2.CU57(QPI1_DRX_DP13)
QPI_CPU0_CPU1_P0P1_DP_14: CPU1.CE47(QPI0_DTX_DP14) CPU2.CT58(QPI1_DRX_DP14)
QPI_CPU0_CPU1_P0P1_DP_15: CPU1.CD48(QPI0_DTX_DP15) CPU2.CM56(QPI1_DRX_DP15)
QPI_CPU0_CPU1_P0P1_DP_16: CPU1.CD50(QPI0_DTX_DP16) CPU2.CL55(QPI1_DRX_DN16)
QPI_CPU0_CPU1_P0P1_DP_17: CPU1.CD52(QPI0_DTX_DP17) CPU2.CF54(QPI1_DRX_DN17)
QPI_CPU0_CPU1_P0P1_DP_18: CPU1.CE51(QPI0_DTX_DP18) CPU2.CF56(QPI1_DRX_DN18)
QPI_CPU0_CPU1_P0P1_DP_19: CPU1.CE49(QPI0_DTX_DP19) CPU2.CE55(QPI1_DRX_DN19)
QPI_CPU0_CPU1_P1P0_CLK_DN: CPU1.CY54(QPI1_CLKTX_DN) CPU2.BK58(QPI0_CLKRX_DP)
QPI_CPU0_CPU1_P1P0_CLK_DP: CPU1.DB54(QPI1_CLKTX_DP) CPU2.BM58(QPI0_CLKRX_DN)
QPI_CPU0_CPU1_P1P0_DN_0: CPU1.DE41(QPI1_DTX_DN0) CPU2.BJ51(QPI0_DRX_DP0)
QPI_CPU0_CPU1_P1P0_DN_1: CPU1.DB42(QPI1_DTX_DN1) CPU2.BF52(QPI0_DRX_DN1)
QPI_CPU0_CPU1_P1P0_DN_2: CPU1.CW41(QPI1_DTX_DN2) CPU2.BE53(QPI0_DRX_DP2)
QPI_CPU0_CPU1_P1P0_DN_3: CPU1.DE43(QPI1_DTX_DN3) CPU2.BE55(QPI0_DRX_DP3)
QPI_CPU0_CPU1_P1P0_DN_4: CPU1.DB44(QPI1_DTX_DN4) CPU2.BF56(QPI0_DRX_DP4)
QPI_CPU0_CPU1_P1P0_DN_5: CPU1.CV42(QPI1_DTX_DN5) CPU2.BF54(QPI0_DRX_DP5)
QPI_CPU0_CPU1_P1P0_DN_6: CPU1.DE45(QPI1_DTX_DN6) CPU2.BF50(QPI0_DRX_DP6)
QPI_CPU0_CPU1_P1P0_DN_7: CPU1.DB46(QPI1_DTX_DN7) CPU2.BD58(QPI0_DRX_DP7)
QPI_CPU0_CPU1_P1P0_DN_8: CPU1.CW43(QPI1_DTX_DN8) CPU2.BE57(QPI0_DRX_DP8)
QPI_CPU0_CPU1_P1P0_DN_9: CPU1.DE47(QPI1_DTX_DN9) CPU2.BM56(QPI0_DRX_DP9)
QPI_CPU0_CPU1_P1P0_DN_10: CPU1.DD48(QPI1_DTX_DN10) CPU2.BN55(QPI0_DRX_DN10)
QPI_CPU0_CPU1_P1P0_DN_11: CPU1.CW45(QPI1_DTX_DN11) CPU2.BM54(QPI0_DRX_DP11)
QPI_CPU0_CPU1_P1P0_DN_12: CPU1.DC49(QPI1_DTX_DN12) CPU2.BN53(QPI0_DRX_DN12)
QPI_CPU0_CPU1_P1P0_DN_13: CPU1.DD50(QPI1_DTX_DN13) CPU2.BP52(QPI0_DRX_DN13)
QPI_CPU0_CPU1_P1P0_DN_14: CPU1.CW47(QPI1_DTX_DN14) CPU2.BN51(QPI0_DRX_DP14)
QPI_CPU0_CPU1_P1P0_DN_15: CPU1.DC51(QPI1_DTX_DN15) CPU2.BP50(QPI0_DRX_DN15)
QPI_CPU0_CPU1_P1P0_DN_16: CPU1.DD52(QPI1_DTX_DN16) CPU2.BN49(QPI0_DRX_DP16)
QPI_CPU0_CPU1_P1P0_DN_17: CPU1.CV48(QPI1_DTX_DN17) CPU2.BG49(QPI0_DRX_DP17)
QPI_CPU0_CPU1_P1P0_DN_18: CPU1.CV46(QPI1_DTX_DN18) CPU2.BP48(QPI0_DRX_DN18)
QPI_CPU0_CPU1_P1P0_DN_19: CPU1.CV44(QPI1_DTX_DN19) CPU2.BR47(QPI0_DRX_DN19)
QPI_CPU0_CPU1_P1P0_DP_0: CPU1.DC41(QPI1_DTX_DP0) CPU2.BG51(QPI0_DRX_DN0)
QPI_CPU0_CPU1_P1P0_DP_1: CPU1.DD42(QPI1_DTX_DP1) CPU2.BH52(QPI0_DRX_DP1)
QPI_CPU0_CPU1_P1P0_DP_2: CPU1.CU41(QPI1_DTX_DP2) CPU2.BG53(QPI0_DRX_DN2)
QPI_CPU0_CPU1_P1P0_DP_3: CPU1.DC43(QPI1_DTX_DP3) CPU2.BG55(QPI0_DRX_DN3)
QPI_CPU0_CPU1_P1P0_DP_4: CPU1.DD44(QPI1_DTX_DP4) CPU2.BH56(QPI0_DRX_DN4)
QPI_CPU0_CPU1_P1P0_DP_5: CPU1.CT42(QPI1_DTX_DP5) CPU2.BH54(QPI0_DRX_DN5)
QPI_CPU0_CPU1_P1P0_DP_6: CPU1.DC45(QPI1_DTX_DP6) CPU2.BH50(QPI0_DRX_DN6)
QPI_CPU0_CPU1_P1P0_DP_7: CPU1.DD46(QPI1_DTX_DP7) CPU2.BF58(QPI0_DRX_DN7)
QPI_CPU0_CPU1_P1P0_DP_8: CPU1.CU43(QPI1_DTX_DP8) CPU2.BG57(QPI0_DRX_DN8)
QPI_CPU0_CPU1_P1P0_DP_9: CPU1.DC47(QPI1_DTX_DP9) CPU2.BP56(QPI0_DRX_DN9)
QPI_CPU0_CPU1_P1P0_DP_10: CPU1.DB48(QPI1_DTX_DP10) CPU2.BL55(QPI0_DRX_DP10)
QPI_CPU0_CPU1_P1P0_DP_11: CPU1.CU45(QPI1_DTX_DP11) CPU2.BP54(QPI0_DRX_DN11)
QPI_CPU0_CPU1_P1P0_DP_12: CPU1.DE49(QPI1_DTX_DP12) CPU2.BL53(QPI0_DRX_DP12)
QPI_CPU0_CPU1_P1P0_DP_13: CPU1.DB50(QPI1_DTX_DP13) CPU2.BM52(QPI0_DRX_DP13)
QPI_CPU0_CPU1_P1P0_DP_14: CPU1.CU47(QPI1_DTX_DP14) CPU2.BR51(QPI0_DRX_DN14)
QPI_CPU0_CPU1_P1P0_DP_15: CPU1.DE51(QPI1_DTX_DP15) CPU2.BM50(QPI0_DRX_DP15)
QPI_CPU0_CPU1_P1P0_DP_16: CPU1.DB52(QPI1_DTX_DP16) CPU2.BR49(QPI0_DRX_DN16)
QPI_CPU0_CPU1_P1P0_DP_17: CPU1.CT48(QPI1_DTX_DP17) CPU2.BJ49(QPI0_DRX_DN17)
QPI_CPU0_CPU1_P1P0_DP_18: CPU1.CT46(QPI1_DTX_DP18) CPU2.BM48(QPI0_DRX_DP18)
QPI_CPU0_CPU1_P1P0_DP_19: CPU1.CT44(QPI1_DTX_DP19) CPU2.BN47(QPI0_DRX_DP19)
QPI_CPU1_CPU0_P0P1_CLK_DN: CPU1.CL53(QPI1_CLKRX_DN) CPU2.CF44(QPI0_CLKTX_DN)
QPI_CPU1_CPU0_P0P1_CLK_DP: CPU1.CJ53(QPI1_CLKRX_DP) CPU2.CD44(QPI0_CLKTX_DP)
QPI_CPU1_CPU0_P0P1_DN_0: CPU1.CK44(QPI1_DRX_DP0) CPU2.BW49(QPI0_DTX_DN0)
QPI_CPU1_CPU0_P0P1_DN_1: CPU1.CL45(QPI1_DRX_DP1) CPU2.BW51(QPI0_DTX_DN1)
QPI_CPU1_CPU0_P0P1_DN_2: CPU1.CK46(QPI1_DRX_DP2) CPU2.BW53(QPI0_DTX_DN2)
QPI_CPU1_CPU0_P0P1_DN_3: CPU1.CL47(QPI1_DRX_DP3) CPU2.BY54(QPI0_DTX_DN3)
QPI_CPU1_CPU0_P0P1_DN_4: CPU1.CM48(QPI1_DRX_DN4) CPU2.BW55(QPI0_DTX_DN4)
QPI_CPU1_CPU0_P0P1_DN_5: CPU1.CN49(QPI1_DRX_DN5) CPU2.BV58(QPI0_DTX_DN5)
QPI_CPU1_CPU0_P0P1_DN_6: CPU1.CM50(QPI1_DRX_DN6) CPU2.BW47(QPI0_DTX_DN6)
QPI_CPU1_CPU0_P0P1_DN_7: CPU1.CN51(QPI1_DRX_DN7) CPU2.BW57(QPI0_DTX_DN7)
QPI_CPU1_CPU0_P0P1_DN_8: CPU1.CV52(QPI1_DRX_DN8) CPU2.BY56(QPI0_DTX_DN8)
QPI_CPU1_CPU0_P0P1_DN_9: CPU1.CU53(QPI1_DRX_DN9) CPU2.BW45(QPI0_DTX_DN9)
QPI_CPU1_CPU0_P0P1_DN_10: CPU1.CP54(QPI1_DRX_DP10) CPU2.CF46(QPI0_DTX_DN10)
QPI_CPU1_CPU0_P0P1_DN_11: CPU1.CR55(QPI1_DRX_DN11) CPU2.BY52(QPI0_DTX_DN11)
QPI_CPU1_CPU0_P0P1_DN_12: CPU1.CT56(QPI1_DRX_DN12) CPU2.CA47(QPI0_DTX_DN12)
QPI_CPU1_CPU0_P0P1_DN_13: CPU1.CR57(QPI1_DRX_DN13) CPU2.CA49(QPI0_DTX_DN13)
QPI_CPU1_CPU0_P0P1_DN_14: CPU1.CP58(QPI1_DRX_DN14) CPU2.CG47(QPI0_DTX_DN14)
QPI_CPU1_CPU0_P0P1_DN_15: CPU1.CK56(QPI1_DRX_DN15) CPU2.CF48(QPI0_DTX_DN15)
QPI_CPU1_CPU0_P0P1_DN_16: CPU1.CJ55(QPI1_DRX_DP16) CPU2.CF50(QPI0_DTX_DN16)
QPI_CPU1_CPU0_P0P1_DN_17: CPU1.CD54(QPI1_DRX_DP17) CPU2.CF52(QPI0_DTX_DN17)
QPI_CPU1_CPU0_P0P1_DN_18: CPU1.CD56(QPI1_DRX_DP18) CPU2.CG51(QPI0_DTX_DN18)
QPI_CPU1_CPU0_P0P1_DN_19: CPU1.CC55(QPI1_DRX_DP19) CPU2.CG49(QPI0_DTX_DN19)
QPI_CPU1_CPU0_P0P1_DP_0: CPU1.CM44(QPI1_DRX_DN0) CPU2.BV50(QPI0_DTX_DP0)
QPI_CPU1_CPU0_P0P1_DP_1: CPU1.CN45(QPI1_DRX_DN1) CPU2.BV52(QPI0_DTX_DP1)
QPI_CPU1_CPU0_P0P1_DP_2: CPU1.CM46(QPI1_DRX_DN2) CPU2.BU53(QPI0_DTX_DP2)
QPI_CPU1_CPU0_P0P1_DP_3: CPU1.CN47(QPI1_DRX_DN3) CPU2.BV54(QPI0_DTX_DP3)
QPI_CPU1_CPU0_P0P1_DP_4: CPU1.CK48(QPI1_DRX_DP4) CPU2.BU55(QPI0_DTX_DP4)
QPI_CPU1_CPU0_P0P1_DP_5: CPU1.CL49(QPI1_DRX_DP5) CPU2.BT58(QPI0_DTX_DP5)
QPI_CPU1_CPU0_P0P1_DP_6: CPU1.CK50(QPI1_DRX_DP6) CPU2.BV48(QPI0_DTX_DP6)
QPI_CPU1_CPU0_P0P1_DP_7: CPU1.CL51(QPI1_DRX_DP7) CPU2.BU57(QPI0_DTX_DP7)
QPI_CPU1_CPU0_P0P1_DP_8: CPU1.CT52(QPI1_DRX_DP8) CPU2.BV56(QPI0_DTX_DP8)
QPI_CPU1_CPU0_P0P1_DP_9: CPU1.CR53(QPI1_DRX_DP9) CPU2.BV46(QPI0_DTX_DP9)
QPI_CPU1_CPU0_P0P1_DP_10: CPU1.CT54(QPI1_DRX_DN10) CPU2.CD46(QPI0_DTX_DP10)
QPI_CPU1_CPU0_P0P1_DP_11: CPU1.CU55(QPI1_DRX_DP11) CPU2.CA51(QPI0_DTX_DP11)
QPI_CPU1_CPU0_P0P1_DP_12: CPU1.CV56(QPI1_DRX_DP12) CPU2.BY48(QPI0_DTX_DP12)
QPI_CPU1_CPU0_P0P1_DP_13: CPU1.CU57(QPI1_DRX_DP13) CPU2.BY50(QPI0_DTX_DP13)
QPI_CPU1_CPU0_P0P1_DP_14: CPU1.CT58(QPI1_DRX_DP14) CPU2.CE47(QPI0_DTX_DP14)
QPI_CPU1_CPU0_P0P1_DP_15: CPU1.CM56(QPI1_DRX_DP15) CPU2.CD48(QPI0_DTX_DP15)
QPI_CPU1_CPU0_P0P1_DP_16: CPU1.CL55(QPI1_DRX_DN16) CPU2.CD50(QPI0_DTX_DP16)
QPI_CPU1_CPU0_P0P1_DP_17: CPU1.CF54(QPI1_DRX_DN17) CPU2.CD52(QPI0_DTX_DP17)
QPI_CPU1_CPU0_P0P1_DP_18: CPU1.CF56(QPI1_DRX_DN18) CPU2.CE51(QPI0_DTX_DP18)
QPI_CPU1_CPU0_P0P1_DP_19: CPU1.CE55(QPI1_DRX_DN19) CPU2.CE49(QPI0_DTX_DP19)
QPI_CPU1_CPU0_P1P0_CLK_DN: CPU1.BM58(QPI0_CLKRX_DN) CPU2.CY54(QPI1_CLKTX_DN)
QPI_CPU1_CPU0_P1P0_CLK_DP: CPU1.BK58(QPI0_CLKRX_DP) CPU2.DB54(QPI1_CLKTX_DP)
QPI_CPU1_CPU0_P1P0_DN_0: CPU1.BJ51(QPI0_DRX_DP0) CPU2.DE41(QPI1_DTX_DN0)
QPI_CPU1_CPU0_P1P0_DN_1: CPU1.BF52(QPI0_DRX_DN1) CPU2.DB42(QPI1_DTX_DN1)
QPI_CPU1_CPU0_P1P0_DN_2: CPU1.BG53(QPI0_DRX_DN2) CPU2.CW41(QPI1_DTX_DN2)
QPI_CPU1_CPU0_P1P0_DN_3: CPU1.BE55(QPI0_DRX_DP3) CPU2.DE43(QPI1_DTX_DN3)
QPI_CPU1_CPU0_P1P0_DN_4: CPU1.BF56(QPI0_DRX_DP4) CPU2.DB44(QPI1_DTX_DN4)
QPI_CPU1_CPU0_P1P0_DN_5: CPU1.BF54(QPI0_DRX_DP5) CPU2.CV42(QPI1_DTX_DN5)
QPI_CPU1_CPU0_P1P0_DN_6: CPU1.BF50(QPI0_DRX_DP6) CPU2.DE45(QPI1_DTX_DN6)
QPI_CPU1_CPU0_P1P0_DN_7: CPU1.BD58(QPI0_DRX_DP7) CPU2.DB46(QPI1_DTX_DN7)
QPI_CPU1_CPU0_P1P0_DN_8: CPU1.BE57(QPI0_DRX_DP8) CPU2.CW43(QPI1_DTX_DN8)
QPI_CPU1_CPU0_P1P0_DN_9: CPU1.BM56(QPI0_DRX_DP9) CPU2.DE47(QPI1_DTX_DN9)
QPI_CPU1_CPU0_P1P0_DN_10: CPU1.BN55(QPI0_DRX_DN10) CPU2.DD48(QPI1_DTX_DN10)
QPI_CPU1_CPU0_P1P0_DN_11: CPU1.BM54(QPI0_DRX_DP11) CPU2.CW45(QPI1_DTX_DN11)
QPI_CPU1_CPU0_P1P0_DN_12: CPU1.BN53(QPI0_DRX_DN12) CPU2.DC49(QPI1_DTX_DN12)
QPI_CPU1_CPU0_P1P0_DN_13: CPU1.BP52(QPI0_DRX_DN13) CPU2.DD50(QPI1_DTX_DN13)
QPI_CPU1_CPU0_P1P0_DN_14: CPU1.BN51(QPI0_DRX_DP14) CPU2.CW47(QPI1_DTX_DN14)
QPI_CPU1_CPU0_P1P0_DN_15: CPU1.BP50(QPI0_DRX_DN15) CPU2.DC51(QPI1_DTX_DN15)
QPI_CPU1_CPU0_P1P0_DN_16: CPU1.BN49(QPI0_DRX_DP16) CPU2.DD52(QPI1_DTX_DN16)
QPI_CPU1_CPU0_P1P0_DN_17: CPU1.BJ49(QPI0_DRX_DN17) CPU2.CV48(QPI1_DTX_DN17)
QPI_CPU1_CPU0_P1P0_DN_18: CPU1.BP48(QPI0_DRX_DN18) CPU2.CV46(QPI1_DTX_DN18)
QPI_CPU1_CPU0_P1P0_DN_19: CPU1.BR47(QPI0_DRX_DN19) CPU2.CV44(QPI1_DTX_DN19)
QPI_CPU1_CPU0_P1P0_DP_0: CPU1.BG51(QPI0_DRX_DN0) CPU2.DC41(QPI1_DTX_DP0)
QPI_CPU1_CPU0_P1P0_DP_1: CPU1.BH52(QPI0_DRX_DP1) CPU2.DD42(QPI1_DTX_DP1)
QPI_CPU1_CPU0_P1P0_DP_2: CPU1.BE53(QPI0_DRX_DP2) CPU2.CU41(QPI1_DTX_DP2)
QPI_CPU1_CPU0_P1P0_DP_3: CPU1.BG55(QPI0_DRX_DN3) CPU2.DC43(QPI1_DTX_DP3)
QPI_CPU1_CPU0_P1P0_DP_4: CPU1.BH56(QPI0_DRX_DN4) CPU2.DD44(QPI1_DTX_DP4)
QPI_CPU1_CPU0_P1P0_DP_5: CPU1.BH54(QPI0_DRX_DN5) CPU2.CT42(QPI1_DTX_DP5)
QPI_CPU1_CPU0_P1P0_DP_6: CPU1.BH50(QPI0_DRX_DN6) CPU2.DC45(QPI1_DTX_DP6)
QPI_CPU1_CPU0_P1P0_DP_7: CPU1.BF58(QPI0_DRX_DN7) CPU2.DD46(QPI1_DTX_DP7)
QPI_CPU1_CPU0_P1P0_DP_8: CPU1.BG57(QPI0_DRX_DN8) CPU2.CU43(QPI1_DTX_DP8)
QPI_CPU1_CPU0_P1P0_DP_9: CPU1.BP56(QPI0_DRX_DN9) CPU2.DC47(QPI1_DTX_DP9)
QPI_CPU1_CPU0_P1P0_DP_10: CPU1.BL55(QPI0_DRX_DP10) CPU2.DB48(QPI1_DTX_DP10)
QPI_CPU1_CPU0_P1P0_DP_11: CPU1.BP54(QPI0_DRX_DN11) CPU2.CU45(QPI1_DTX_DP11)
QPI_CPU1_CPU0_P1P0_DP_12: CPU1.BL53(QPI0_DRX_DP12) CPU2.DE49(QPI1_DTX_DP12)
QPI_CPU1_CPU0_P1P0_DP_13: CPU1.BM52(QPI0_DRX_DP13) CPU2.DB50(QPI1_DTX_DP13)
QPI_CPU1_CPU0_P1P0_DP_14: CPU1.BR51(QPI0_DRX_DN14) CPU2.CU47(QPI1_DTX_DP14)
QPI_CPU1_CPU0_P1P0_DP_15: CPU1.BM50(QPI0_DRX_DP15) CPU2.DE51(QPI1_DTX_DP15)
QPI_CPU1_CPU0_P1P0_DP_16: CPU1.BR49(QPI0_DRX_DN16) CPU2.DB52(QPI1_DTX_DP16)
QPI_CPU1_CPU0_P1P0_DP_17: CPU1.BG49(QPI0_DRX_DP17) CPU2.CT48(QPI1_DTX_DP17)
QPI_CPU1_CPU0_P1P0_DP_18: CPU1.BM48(QPI0_DRX_DP18) CPU2.CT46(QPI1_DTX_DP18)
QPI_CPU1_CPU0_P1P0_DP_19: CPU1.BN47(QPI0_DRX_DP19) CPU2.CT44(QPI1_DTX_DP19)
SMB_0_ME_PCH_SCL: R623.2 WBG1.BF32(MEXP_SMBCLK0)
SMB_0_ME_PCH_SDA: R622.2 WBG1.BJ33(MEXP_SMBDATA0)
SMB_1_ME_PCH_SCL: R879.2 WBG1.BH32(MEXP_SMBCLK1)
SMB_1_ME_PCH_SDA: R878.2 ; also on sheet 174
SMB_1_ME_PCH_SDA_LT_STRAP: R365.1 WBG1.BF30(MEXP_SMBDATA1) ; also on sheet 174
SMB_2_ME_PCH_SCL: R877.2 WBG1.BH30(MEXP_SMBCLK2)
SMB_2_ME_PCH_SDA: R876.2 WBG1.BJ37(MEXP_SMBDATA2)
SMB_HOST_3V3_CLK: R619.2 U41.4(S2) ; also on sheet 58
SMB_HOST_3V3_DATA: R618.2 U41.1(S1) ; also on sheet 58
SMB_HOST_STBY_LVC3_CLK: U41.3(D2) ; also on sheet 47 55 74 77 90
SMB_HOST_STBY_LVC3_DATA: U41.6(D1) ; also on sheet 47 55 74 77 90
SMB_PMBUS_BMC_STBY_LVC3_CLK: R721.2 ; also on sheet 60 74 77 90
SMB_PMBUS_BMC_STBY_LVC3_DATA: R717.2 ; also on sheet 60 74 77 90
SMB_PMBUS_CLK: R721.1 ; also on sheet 93
SMB_PMBUS_DATA: R717.1 ; also on sheet 93
SMB_VR_STBY_LVC3_CLK: R875.2 ; also on sheet 16 21 26 31 35 39 74
SMB_VR_STBY_LVC3_DATA: R874.2 ; also on sheet 16 21 26 31 35 39 74
TP_PCI_PME_N: TP184.1 WBG1.C35(PME#)

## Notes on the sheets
sheet 161
- SMBUS (2/4)
- FAB1 REV018 20150420
- FAB1 REV018 20150420
- Remove components
- Remove components
- FAB1 REV013 20150413
- Change to 75.04001.07C
- FAB1 REV018 20150420
- Remove components
- Change to 75.00138.07C
- FAB2 REV001 20150610
- FAB1 REV004 20150320
- FAB1 20150211
sheet 162
- SMBUS (4/4)
- FAB1 REV004 20150320
- Delete redundant components.
- FAB1 REV001 20150316
- Delete components
- FAB1 REV004 20150319
sheet 163
- CPU2 - QPI (1/2)
- Layout Note :
- Angle routing of >= 30 degree between signal routing in the inter layers
- are highly recommended.
- - Less than 25 mils parallel routing in the pin field is allowed for non-interleaving
- between TX and RX.
- - Less than 5 mils parallel routing in the pin field is allowed for interleaving
- between TX and RX.
- - Total bus length reduction is 2" for less than 250 mils parallel routing or 0.4"
- for every 50 mils in the pin field for non-interleaving between TX and RX.
- - Total bus length reduction is 7" for less than 250 mils parallel routing or 1.5"
- for every 50 mils in the pin field for interleaving between TX and RX.
sheet 164
- CPU1 - QPI (1/2)
- Layout Note :
- Angle routing of >= 30 degree between signal routing in the inter layers
- are highly recommended.
- - Less than 25 mils parallel routing in the pin field is allowed for non-interleaving
- between TX and RX.
- - Less than 5 mils parallel routing in the pin field is allowed for interleaving
- between TX and RX.
- - Total bus length reduction is 2" for less than 250 mils parallel routing or 0.4"
- for every 50 mils in the pin field for non-interleaving between TX and RX.
- - Total bus length reduction is 7" for less than 250 mils parallel routing or 1.5"
- for every 50 mils in the pin field for interleaving between TX and RX.
sheet 165
- CPU1 - QPI (2/2)
- Layout Note :
- Angle routing of >= 30 degree between signal routing in the inter layers
- are highly recommended.
- - Less than 25 mils parallel routing in the pin field is allowed for non-interleaving
- between TX and RX.
- - Less than 5 mils parallel routing in the pin field is allowed for interleaving
- between TX and RX.
- - Total bus length reduction is 2" for less than 250 mils parallel routing or 0.4"
- for every 50 mils in the pin field for non-interleaving between TX and RX.
- - Total bus length reduction is 7" for less than 250 mils parallel routing or 1.5"
- for every 50 mils in the pin field for interleaving between TX and RX.
sheet 166
- WELLSBURG - CLOCK/MICS
- One PCI clock must be supplied to CLKIN_PCILOOPBACK
  pin on PCH at all times even if there are no PCI
  devices present on the platform.
- TO VCCRTCEXT PIN DESIGN NOTE:
  VCCRTCEXT_NCTF NEEDS TO BE SHORTED DIRECTLY
- CAD NOTE:
  TIE TRACES TOGETHER CLOSE TO PINS
  WITH LENGTH NO LONGER THAN 1 INCHE TO RESISTOR
- CAD NOTE:
  PLACE PRECISION RESISTOR
  WITHIN 450 MILS TRACE OF PCH
- LT debug mode is enabled when pulled low prior to
  PCH_PWROK.
  Notes:
  1.         External pull up resistor is required.
  2.         This signal is in the Core Well.
- This Signal has a weak internal pull-up.
  0= Configures DMI for AC coupling mode.
  1 = Configures DMI for DC coupling mode.
  Note:
  1.    The internal pull-up is disabled after PLTRST# deasserts.
  2.    This signal should be always pull low as Wellsburg only
  support AC coupling mode.
  3.    This signal is in the Core well.
- Requires external pull-up resistors to P3V3.
- CAD NOTE:
  PLACE PRECISION RESISTOR WITHIN
  500 MILS TRACE OF PCH
- FAB1 20150310
- These signals are not used when the PCH is in
  Native isCLK or PCH Hybrid Mode and must be
  terminated properly using one (for REF14 input)
  or two (for differential inputs) separate 10kohm
  pulldown resistors. This is for reliability concerns
  during platform power-on.
sheet 167
- CPU2 - QPI (2/2)
- Layout Note :
- Angle routing of >= 30 degree between signal routing in the inter layers
- are highly recommended.
- - Less than 25 mils parallel routing in the pin field is allowed for non-interleaving
- between TX and RX.
- - Less than 5 mils parallel routing in the pin field is allowed for interleaving
- between TX and RX.
- - Total bus length reduction is 2" for less than 250 mils parallel routing or 0.4"
- for every 50 mils in the pin field for non-interleaving between TX and RX.
- - Total bus length reduction is 7" for less than 250 mils parallel routing or 1.5"
- for every 50 mils in the pin field for interleaving between TX and RX.
